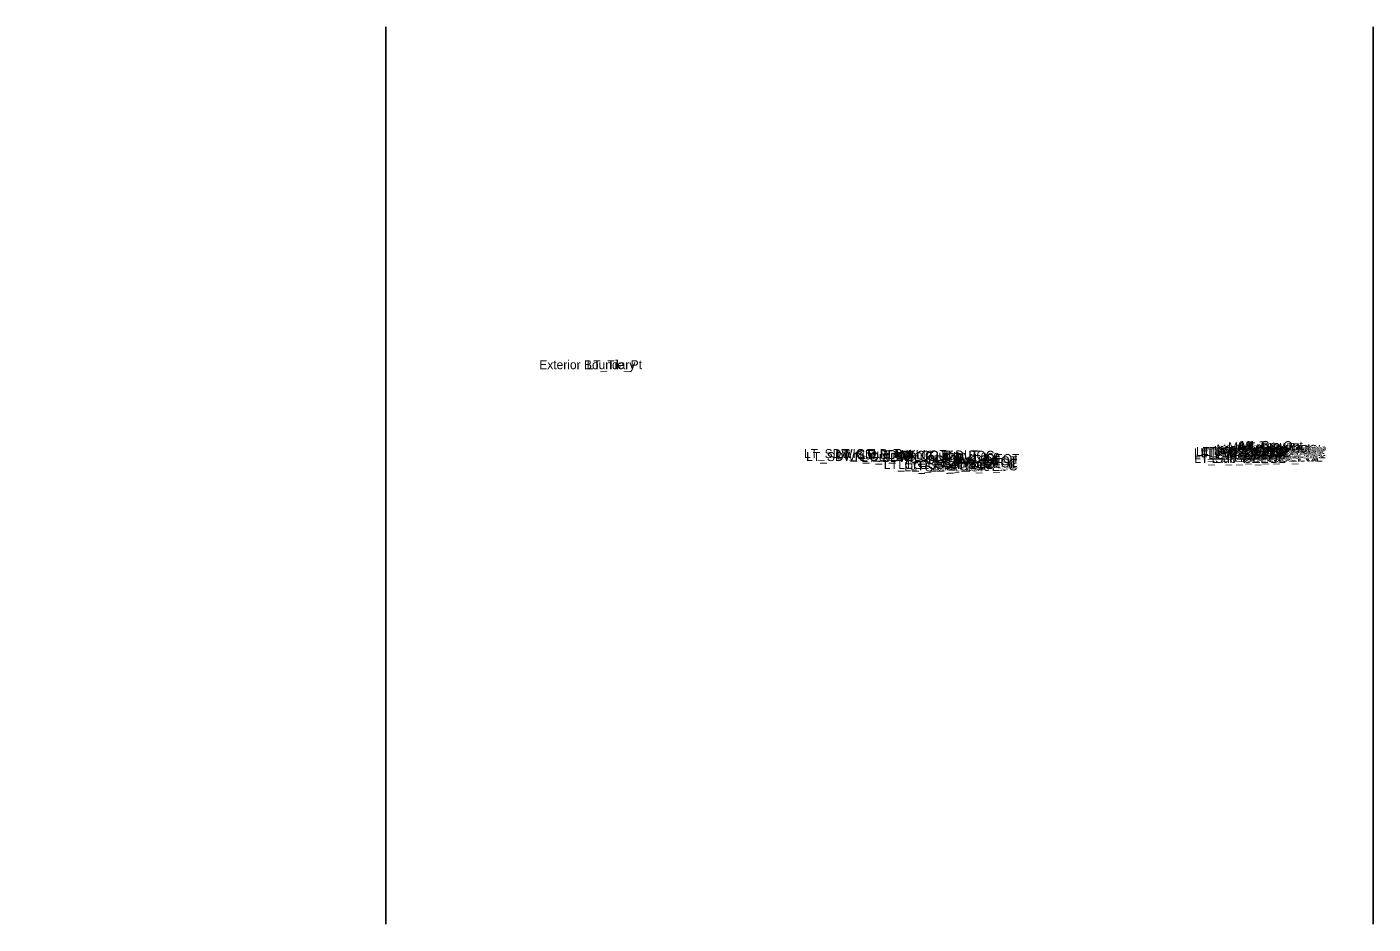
# Model space of a CAD drawing. Extents: x 0 to 6300, y -50 to 9550.
# Drawn here: x 3000 to 3150, y 2450 to 2550 of the extents above; entities that cross this region are included whole.
import ezdxf

# ---------------------------------------------------------------- set-up
doc = ezdxf.new("R2010")
doc.units = 0
for name, color, linetype in [('Default', 7, 'Continuous'), ('Prop XS Exc Vertical Line 1', 7, 'Continuous'), ('Prop XS Exc Vertical Line 2', 7, 'Continuous')]:
    doc.layers.add(name, color=color, linetype=linetype)

msp = doc.modelspace()

# ---------------------------------------------------------------- linework, layer by layer
at = {"layer": 'Prop XS Exc Vertical Line 1'}
msp.add_line((3040, 2550), (3040, 2450), dxfattribs=at)
at = {"layer": 'Prop XS Exc Vertical Line 2'}
msp.add_line((3150, 2550), (3150, 2450), dxfattribs=at)

# ---------------------------------------------------------------- texts
at = {"layer": 'Default'}
for s, height, p in [('Exterior Boundary', 1, (3057.09, 2511.85)), ('LT_Tie_Pt', 1, (3062.37, 2511.85)), ('MI_Top In', 1, (3133.84, 2502.7)), ('MI_Top Out', 1, (3135.1, 2502.82)), ('MI_Crown', 1, (3135.24, 2502.85)), ('MI_Face Out', 1, (3135.31, 2502.57)), ('LT_SDWK_Out_Top', 1, (3086.58, 2501.94)), ('LT_SDWK_Out_Bot', 1, (3086.83, 2501.61)), ('LT_CSLP_Pnt', 1, (3090.1, 2501.94)), ('LT_Sub_Trench_Out_DLT', 1, (3090.21, 2501.79)), ('LT_SDWK_In_Top', 1, (3092.74, 2501.84)), ('LT_SDWK_In_Bot', 1, (3092.99, 2501.51)), ('LT_CG_Top_BOC', 1, (3096.81, 2501.75)), ('LT_CG_Top_Face', 1, (3097.34, 2501.75)), ('LT_CG_Top_Gut', 1, (3097.87, 2501.25)), ('LT_PV2_OEOT', 1, (3100.99, 2501.14)), ('LT_PV1_OEOT', 1, (3101.23, 2501.39)), ('LT_PV2_OEEOP', 1, (3130.04, 2502.04)), ('LT_PV3_OEEOP', 1, (3130.04, 2501.79)), ('LT_Sub_OEEOP', 1, (3130.08, 2501.41)), ('LT_PV1_OEEOP', 1, (3130.27, 2502.16)), ('LT_PV2_IEEOP', 1, (3130.8, 2502.04)), ('LT_PV1_IEEOP', 1, (3131.04, 2502.16)), ('LT_PV2_PGL1', 1, (3131.63, 2502.04)), ('LT_PV3_PGL1', 1, (3131.63, 2501.79)), ('LT_PV2_PGL', 1, (3132.01, 2502.04)), ('LT_PV4_PGL', 1, (3132.01, 2501.41)), ('LT_PV1_PGL', 1, (3132.25, 2502.29)), ('MI_Face In', 1, (3132.55, 2502.45)), ('MI_Bot In', 1, (3133.72, 2502.29)), ('RT_PV2_OEEOP', 1, (3133.92, 2502.16)), ('RT_PV3_OEEOP', 1, (3133.92, 2501.91)), ('RT_Sub_OEEOP', 1, (3133.96, 2501.53)), ('RT_PV1_OEEOP', 1, (3134.16, 2502.28)), ('RT_PV2_IEEOP', 1, (3134.68, 2502.16)), ('RT_PV1_IEEOP', 1, (3134.92, 2502.28)), ('RT_PV2_PGL1', 1, (3135.52, 2502.16)), ('RT_PV3_PGL1', 1, (3135.52, 2501.91)), ('RT_PV2_PGL', 1, (3135.9, 2502.16)), ('RT_PV4_PGL', 1, (3135.9, 2501.53)), ('RT_PV1_PGL', 1, (3136.13, 2502.41)), ('MI_Bot Out', 1, (3136.5, 2502.41)), ('LT_CG1_Shelf_Out', 1, (3095.48, 2500.72)), ('LT_CG_Bot_BOC', 1, (3097.09, 2500.73)), ('LT_Sub_OEOP', 1, (3097.77, 2500.46)), ('LT_Sub_OEOT_CG', 1, (3098.44, 2500.56)), ('LT_PV3_OEOT', 1, (3100.99, 2500.89)), ('LT_Sub_OEOT', 1, (3101.04, 2500.52)), ('LT_CG_Bot_IE', 1, (3101.34, 2500.81)), ('-', 0.0001, (3000, 2500))]:
    msp.add_text(s, height=height, dxfattribs=at).set_placement(p)

doc.saveas('drawing.dxf')
